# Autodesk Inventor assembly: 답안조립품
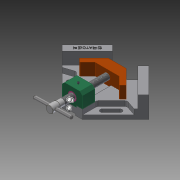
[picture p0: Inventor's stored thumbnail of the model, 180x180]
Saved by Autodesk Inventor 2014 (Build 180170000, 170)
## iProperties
Created: 2019-04
Part Number: 답안조립품
Document SubType Name: Assembly
Designer: kh
Author: kh
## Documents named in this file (11)
- C:\Users\kh\Desktop\490407V1009\답안조립품.iam
- C:\Users\kh\Desktop\490407V1009\베이스.ipt
- C:\Users\kh\Desktop\490407V1009\리드스크류.ipt
- C:\Users\kh\Desktop\490407V1009\멈춤나사 M4x5.ipt
- C:\Users\kh\Desktop\490407V1009\멈춤나사 M4x10.ipt
- C:\Users\kh\Desktop\490407V1009\볼트 M4x16.ipt
- C:\Users\kh\Desktop\490407V1009\부시.ipt
- C:\Users\kh\Desktop\490407V1009\서포트.ipt
- C:\Users\kh\Desktop\490407V1009\조.ipt
- C:\Users\kh\Desktop\490407V1009\평행 핀 2.5x24.ipt
- C:\Users\kh\Desktop\490407V1009\핸들.ipt
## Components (1 placed, 1 different names)
1. 핸들:1 — Mate:7, Mate:9, Mate:10
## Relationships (3: Mate 3)
- Mate:7: 핸들:1
- Mate:9: 핸들:1
- Mate:10: 핸들:1
